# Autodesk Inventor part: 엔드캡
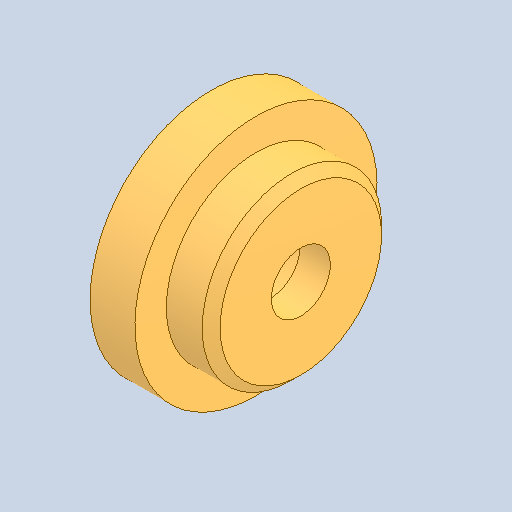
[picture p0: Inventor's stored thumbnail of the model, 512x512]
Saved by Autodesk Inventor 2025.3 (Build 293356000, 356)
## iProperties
Created: 2026-01
Part Number: 엔드캡
Material: 강철, 연강
Document SubType Name: Modeling
Designer: PC-13
Density: 7.85 g/cm^3
Appearance: 기본값
Author: jhkim
Sending System: Autodesk Inventor 2026
Preprocessor: ST-DEVELOPER v20.1
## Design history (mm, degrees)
feature "솔리드1"
node "솔리드2"
